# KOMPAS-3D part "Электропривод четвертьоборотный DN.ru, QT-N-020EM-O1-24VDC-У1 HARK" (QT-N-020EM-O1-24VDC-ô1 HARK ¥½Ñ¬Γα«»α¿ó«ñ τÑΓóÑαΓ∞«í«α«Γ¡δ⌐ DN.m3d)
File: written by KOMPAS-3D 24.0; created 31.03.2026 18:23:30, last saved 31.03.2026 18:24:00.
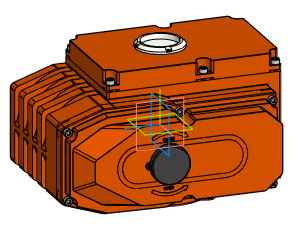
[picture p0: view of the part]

Document properties: Автор: DN.RU; Полное имя файла: D:\PROJECT CAD\DN.RU\...195\Исходники\24В\QT-N-020EM-O1-24VDC-У1 HARK Электропривод четвертьоборотный DN.ru\QT-N-020EM-O1-24VDC-У1 HARK Электропривод четвертьоборотный DN.m3d

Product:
- Body: Твердое тело1  | qty 1
    Масса: 37.407802
- Part/product: Электропривод четвертьоборотный DN.ru  | designation QT-N-020EM-O1-24VDC-У1 HARK
    Масса: 8.9
    Раздел спецификации: Прочие изделия
    Комментарий: D300-05871
    Примечание: D300-05877
    additional columns: Сталь

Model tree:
1. Твердое тело1  (labels: Твердое тело1)

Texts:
  QT-N-020EM-O1-24VDC-У1 HARK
